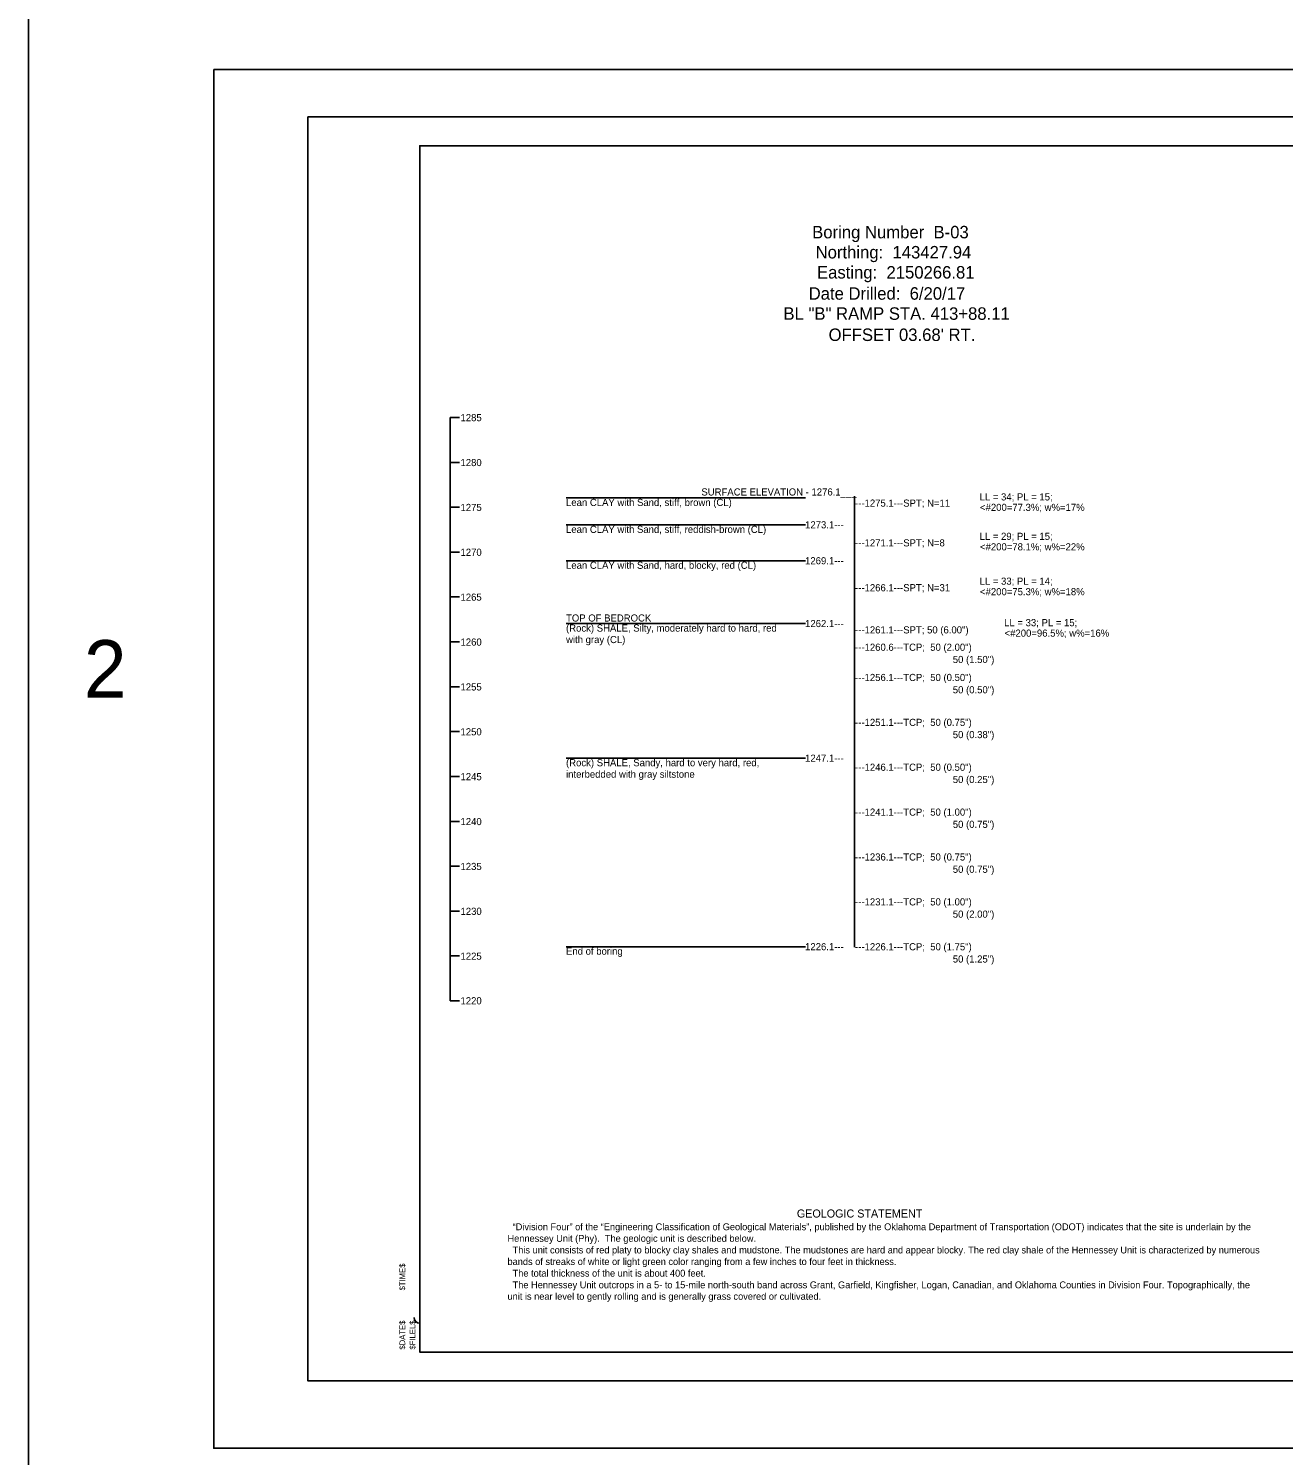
# Model space of a CAD drawing. Extents: x 2150162 to 2150245, y 143729 to 143865.
# Drawn here: x 2150161.57 to 2150183.41, y 143810.76 to 143835.6 of the extents above; entities that cross this region are included whole.
import ezdxf

# ---------------------------------------------------------------- set-up
doc = ezdxf.new("R2010")
doc.units = 0
for name, color, linetype in [('Bridge Border', 7, 'Continuous'), ('Default', 7, 'Continuous'), ('S', 7, 'Continuous'), ('SHT_Plot_Shape_Full', 7, 'Continuous'), ('SHT_Plot_Shape_Half', 7, 'Continuous'), ('SHT_Plot_Stamp', 7, 'Continuous'), ('SHT_Sheet_Border', 7, 'Continuous'), ('Text', 7, 'Continuous')]:
    doc.layers.add(name, color=color, linetype=linetype)

# ---------------------------------------------------------------- blocks, each defined once
blk = doc.blocks.new('Stamp_Plot_Stamp')
at = {"layer": 'SHT_Plot_Stamp'}
for s, p in [('$TIME$', (1.695, 1.572)), ('$DATE$', (1.695, 0.542)), ('$FILEL$', (1.873, 0.542))]:
    blk.add_text(s, height=0.1, rotation=90, dxfattribs=at).set_placement(p)

msp = doc.modelspace()

# ---------------------------------------------------------------- linework, layer by layer
at = {"layer": 'Bridge Border'}
msp.add_arc((2150168.379, 143813.163), 0.1, 180, 270, dxfattribs=at)
at = {"layer": 'Default'}
msp.add_line((2150168.905, 143818.675), (2150168.905, 143828.832), dxfattribs=at)
for points in [[(2150168.905, 143828.832), (2150169.071, 143828.832)], [(2150168.905, 143828.05), (2150169.071, 143828.05)], [(2150168.905, 143827.269), (2150169.071, 143827.269)], [(2150170.924, 143827.432), (2150175.09, 143827.432)], [(2150175.946, 143827.459), (2150175.946, 143819.613)], [(2150170.924, 143826.963), (2150175.09, 143826.963)], [(2150168.905, 143826.488), (2150169.071, 143826.488)], [(2150170.924, 143826.338), (2150175.09, 143826.338)], [(2150168.905, 143825.707), (2150169.071, 143825.707)], [(2150170.924, 143825.244), (2150175.09, 143825.244)], [(2150168.905, 143824.925), (2150169.071, 143824.925)], [(2150168.905, 143824.144), (2150169.071, 143824.144)], [(2150168.905, 143823.363), (2150169.071, 143823.363)], [(2150170.924, 143822.901), (2150175.09, 143822.901)], [(2150168.905, 143822.582), (2150169.071, 143822.582)], [(2150168.905, 143821.8), (2150169.071, 143821.8)], [(2150168.905, 143821.019), (2150169.071, 143821.019)], [(2150168.905, 143820.238), (2150169.071, 143820.238)], [(2150170.924, 143819.619), (2150175.09, 143819.619)], [(2150168.905, 143819.457), (2150169.071, 143819.457)], [(2150168.905, 143818.675), (2150169.071, 143818.675)]]:
    msp.add_lwpolyline(points, dxfattribs=at)
at = {"layer": 'S'}
msp.add_lwpolyline([(2150203.404, 143784.341), (2150161.568, 143784.341), (2150161.568, 143865.061), (2150203.404, 143865.061)], close=True, dxfattribs=at)
at = {"layer": 'SHT_Plot_Shape_Full'}
msp.add_lwpolyline([(2150164.792, 143834.888), (2150200.792, 143834.888), (2150200.792, 143810.888), (2150164.792, 143810.888)], close=True, dxfattribs=at)
at = {"layer": 'SHT_Plot_Shape_Half'}
msp.add_lwpolyline([(2150166.429, 143834.063), (2150200.429, 143834.063), (2150200.429, 143812.063), (2150166.429, 143812.063)], close=True, dxfattribs=at)
at = {"layer": 'SHT_Sheet_Border'}
msp.add_lwpolyline([(2150199.879, 143812.563), (2150168.379, 143812.563), (2150168.379, 143833.563), (2150199.879, 143833.563)], close=True, dxfattribs=at)

# ---------------------------------------------------------------- block references
at = {"layer": 'SHT_Plot_Stamp'}
msp.add_blockref('Stamp_Plot_Stamp', (2150166.429, 143812.063), dxfattribs=at)

# ---------------------------------------------------------------- texts
at = {"layer": 'Default'}
for s, height, p in [('Boring Number  B-03', 0.217, (2150175.208, 143831.95)), ('Northing:  143427.94', 0.217, (2150175.268, 143831.6)), ('Easting:  2150266.81', 0.217, (2150175.292, 143831.25)), ('Date Drilled:  6/20/17', 0.217, (2150175.147, 143830.882)), ('BL "B" RAMP STA. 413+88.11', 0.217, (2150174.708, 143830.532)), ("OFFSET 03.68' RT.", 0.217, (2150175.494, 143830.163)), ('1285', 0.124, (2150169.087, 143828.767)), ('1280', 0.124, (2150169.087, 143827.985)), ('SURFACE ELEVATION - 1276.1___', 0.124, (2150173.28, 143827.473)), ('LL = 34; PL = 15;', 0.124, (2150178.122, 143827.387)), ('1275', 0.124, (2150169.087, 143827.204)), ('Lean CLAY with Sand, stiff, brown (CL)', 0.124, (2150170.924, 143827.291)), ('---1275.1---SPT; N=11', 0.124, (2150175.955, 143827.279)), ('<#200=77.3%; w%=17%', 0.124, (2150178.13, 143827.205)), ('1273.1---', 0.124, (2150175.085, 143826.901)), ('Lean CLAY with Sand, stiff, reddish-brown (CL)', 0.124, (2150170.924, 143826.822)), ('LL = 29; PL = 15;', 0.124, (2150178.122, 143826.701)), ('1270', 0.124, (2150169.087, 143826.423)), ('---1271.1---SPT; N=8', 0.124, (2150175.955, 143826.587)), ('<#200=78.1%; w%=22%', 0.124, (2150178.13, 143826.518)), ('Lean CLAY with Sand, hard, blocky, red (CL)', 0.124, (2150170.924, 143826.197)), ('1269.1---', 0.124, (2150175.085, 143826.276)), ('LL = 33; PL = 14;', 0.124, (2150178.122, 143825.92)), ('1265', 0.124, (2150169.087, 143825.642)), ('---1266.1---SPT; N=31', 0.124, (2150175.955, 143825.806)), ('<#200=75.3%; w%=18%', 0.124, (2150178.13, 143825.737)), ('TOP OF BEDROCK', 0.124, (2150170.924, 143825.279)), ('(Rock) SHALE, Silty, moderately hard to hard, red', 0.124, (2150170.924, 143825.104)), ('1262.1---', 0.124, (2150175.085, 143825.182)), ('LL = 33; PL = 15;', 0.124, (2150178.55, 143825.198)), ('1260', 0.124, (2150169.087, 143824.86)), ('with gray (CL)', 0.124, (2150170.924, 143824.904)), ('---1261.1---SPT; 50 (6.00")', 0.124, (2150175.955, 143825.072)), ('<#200=96.5%; w%=16%', 0.124, (2150178.558, 143825.016)), ('---1260.6---TCP;  50 (2.00")', 0.124, (2150175.955, 143824.77)), ('50 (1.50")', 0.124, (2150177.656, 143824.557)), ('---1256.1---TCP;  50 (0.50")', 0.124, (2150175.955, 143824.244)), ('1255', 0.124, (2150169.087, 143824.079)), ('50 (0.50")', 0.124, (2150177.656, 143824.03)), ('---1251.1---TCP;  50 (0.75")', 0.124, (2150175.955, 143823.462)), ('1250', 0.124, (2150169.087, 143823.298)), ('50 (0.38")', 0.124, (2150177.656, 143823.249)), ('(Rock) SHALE, Sandy, hard to very hard, red,', 0.124, (2150170.924, 143822.76)), ('1247.1---', 0.124, (2150175.085, 143822.839)), ('---1246.1---TCP;  50 (0.50")', 0.124, (2150175.955, 143822.681)), ('1245', 0.124, (2150169.087, 143822.517)), ('interbedded with gray siltstone', 0.124, (2150170.924, 143822.56)), ('50 (0.25")', 0.124, (2150177.656, 143822.468)), ('---1241.1---TCP;  50 (1.00")', 0.124, (2150175.955, 143821.9)), ('1240', 0.124, (2150169.087, 143821.735)), ('50 (0.75")', 0.124, (2150177.656, 143821.687)), ('1235', 0.124, (2150169.087, 143820.954)), ('---1236.1---TCP;  50 (0.75")', 0.124, (2150175.955, 143821.119)), ('50 (0.75")', 0.124, (2150177.656, 143820.905)), ('1230', 0.124, (2150169.087, 143820.173)), ('---1231.1---TCP;  50 (1.00")', 0.124, (2150175.955, 143820.337)), ('50 (2.00")', 0.124, (2150177.656, 143820.124)), ('1225', 0.124, (2150169.087, 143819.392)), ('End of boring', 0.124, (2150170.924, 143819.479)), ('1226.1---', 0.124, (2150175.085, 143819.557)), ('---1226.1---TCP;  50 (1.75")', 0.124, (2150175.955, 143819.556)), ('50 (1.25")', 0.124, (2150177.656, 143819.343)), ('1220', 0.124, (2150169.087, 143818.616))]:
    msp.add_text(s, height=height, dxfattribs=at).set_placement(p)
at = {"layer": 'S'}
msp.add_text('2', height=1, dxfattribs=at).set_placement((2150162.531, 143823.955))
at = {"layer": 'Text'}
for s, height, p in [('GEOLOGIC STATEMENT', 0.14, (2150174.942, 143814.904)), ('  “Division Four” of the “Engineering Classification of Geological Materials”, published by the Oklahoma Department of Transportation (ODOT) indicates that the site is underlain by the ', 0.12, (2150169.905, 143814.683)), ('Hennessey Unit (Phy).  The geologic unit is described below. ', 0.12, (2150169.905, 143814.481)), ('  This unit consists of red platy to blocky clay shales and mudstone. The mudstones are hard and appear blocky. The red clay shale of the Hennessey Unit is characterized by numerous ', 0.12, (2150169.905, 143814.279)), ('bands of streaks of white or light green color ranging from a few inches to four feet in thickness. ', 0.12, (2150169.905, 143814.077)), ('  The total thickness of the unit is about 400 feet.', 0.12, (2150169.905, 143813.875)), ('unit is near level to gently rolling and is generally grass covered or cultivated.', 0.12, (2150169.905, 143813.472)), ('  The Hennessey Unit outcrops in a 5- to 15-mile north-south band across Grant, Garfield, Kingfisher, Logan, Canadian, and Oklahoma Counties in Division Four. Topographically, the ', 0.12, (2150169.905, 143813.672))]:
    msp.add_text(s, height=height, dxfattribs=at).set_placement(p)

doc.saveas('drawing.dxf')
